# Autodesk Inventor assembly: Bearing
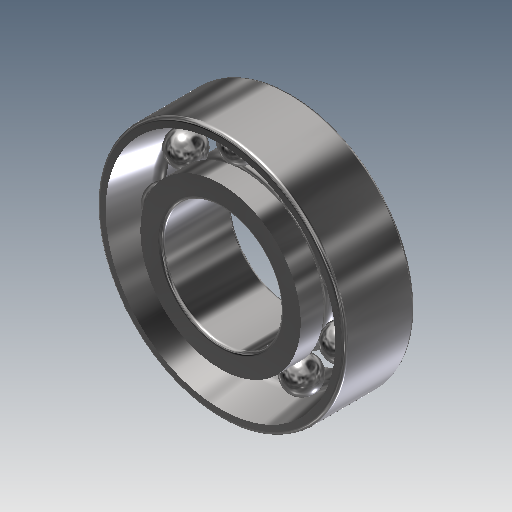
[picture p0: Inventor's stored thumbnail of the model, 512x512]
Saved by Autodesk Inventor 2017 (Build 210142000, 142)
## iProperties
ClientObjectVersion: 1
Created: 2019-02
Part Number: Bearing
Document SubType Name: Assembly
Designer: user
Author: user
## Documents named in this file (2)
- C:\Users\user\Desktop\Ensamble reductor de velocidad\Ensamble\Design Accelerator\Bearing3.iam
- C:\Users\user\Documents\Inventor\Content Center Files\R2017\en-US\BS 292 (II)\BS 292_ Part 1 - 7004 - 20 x 42 x 12.ipt
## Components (1 placed, 1 different names)
1. BS 292: Part 1 (II) - Metric 7004 - 20 x 42 x 12:1
